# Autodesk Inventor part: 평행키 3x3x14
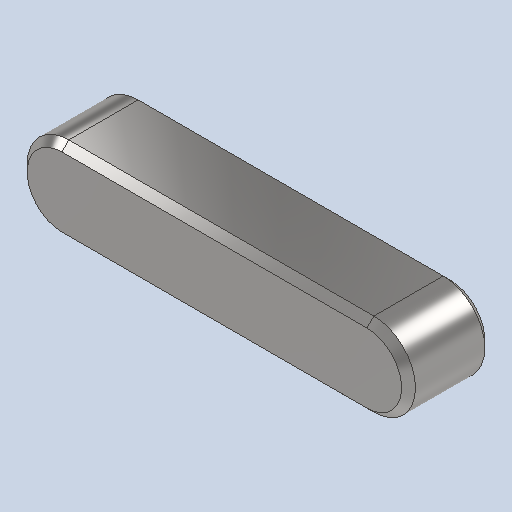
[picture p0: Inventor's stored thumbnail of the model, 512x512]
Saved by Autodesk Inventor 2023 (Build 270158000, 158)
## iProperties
Created: 2024-09
Part Number: 평행키 3x3x14
Material: 강철, 연강
Description: 키 및 해당 키홈
Document SubType Name: Modeling
Designer: home
Density: 7.85 g/cm^3
Appearance: 기본값
Author: jhkim
Sending System: Autodesk Inventor 2025
Preprocessor: ST-DEVELOPER v20
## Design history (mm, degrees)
feature "Solid1"
node "솔리드1"
